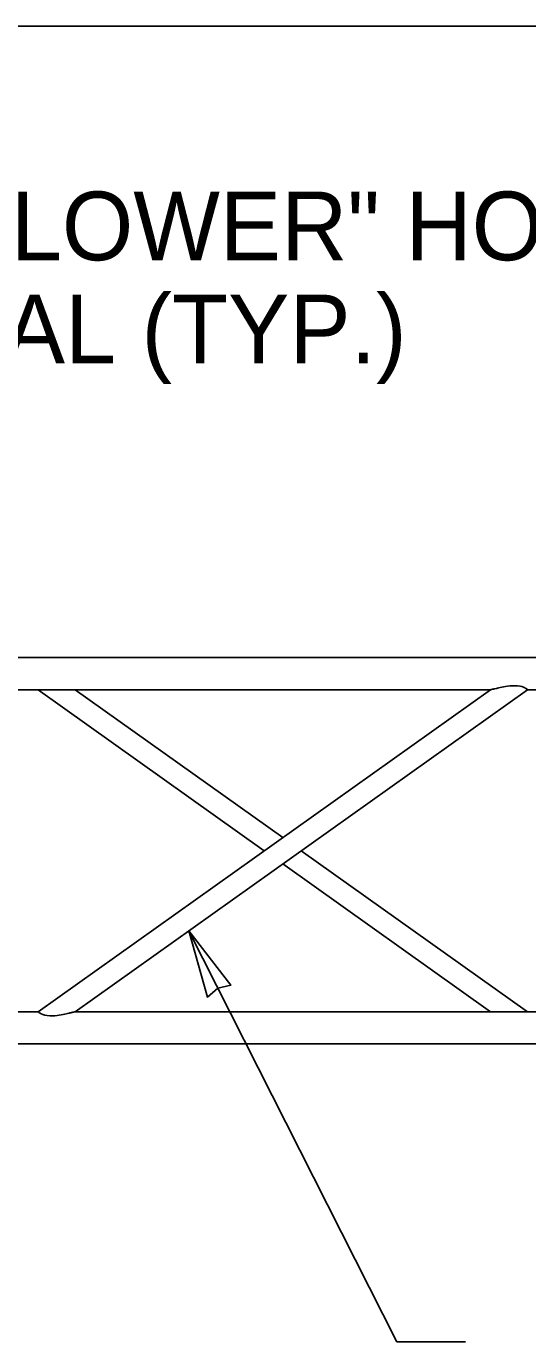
# Model space of a CAD drawing. Extents: x 99862 to 104211, y 98939 to 111076.
# Drawn here: x 101548.3 to 101665.2, y 101768.6 to 102075 of the extents above; entities that cross this region are included whole.
import ezdxf

# ---------------------------------------------------------------- set-up
doc = ezdxf.new("R2010")
doc.units = 0
for name, color, linetype in [('Level 15', 7, 'Continuous'), ('Level 20', 7, 'Continuous'), ('Level 6', 7, 'Continuous'), ('Level 60', 7, 'Continuous')]:
    doc.layers.add(name, color=color, linetype=linetype)

msp = doc.modelspace()

# ---------------------------------------------------------------- linework, layer by layer
at = {"layer": 'Level 15'}
for p in [(101586.13, 101864.31), (101650.65, 101768.61)]:
    msp.add_line(p, (101634.65, 101768.61), dxfattribs=at)
msp.add_lwpolyline([(101586.13, 101864.31), (101590.47, 101848.89), (101592.9, 101850.93), (101595.98, 101851.67)], close=True, dxfattribs=at)
at = {"layer": 'Level 6'}
for p, q in [((101808.38, 101927.97), (100925.37, 101927.97)), ((101656.49, 101920.47), (101440.59, 101920.47)), ((101551, 101920.47), (101603.75, 101882.97)), ((101551, 101845.47), (101656.49, 101920.47)), ((101559.63, 101920.47), (101608.06, 101886.04)), ((101559.63, 101845.47), (101665.12, 101920.47)), ((101673.92, 101920.47), (101665.12, 101920.47)), ((101612.38, 101882.97), (101665.12, 101845.47)), ((101608.06, 101879.9), (101656.49, 101845.47)), ((101551, 101845.47), (101546.08, 101845.47)), ((101779.42, 101845.47), (101559.63, 101845.47)), ((101808.38, 101837.97), (100925.37, 101837.97))]:
    msp.add_line(p, q, dxfattribs=at)
for points, degree in [([(101665.12, 101920.47), (101665.13, 101920.47), (101665.1, 101920.46), (101664.97, 101920.7), (101663.57, 101921.45), (101660.85, 101921.41), (101659.12, 101921.09), (101657.67, 101920.75), (101657.33, 101920.67), (101657.03, 101920.6), (101656.8, 101920.54), (101656.63, 101920.5), (101656.54, 101920.48), (101656.5, 101920.47), (101656.5, 101920.47), (101656.49, 101920.47)], 3), ([(101656.49, 101920.47), (101656.5, 101920.47), (101656.5, 101920.47), (101656.5, 101920.47)], 2), ([(101665.12, 101920.47), (101665.12, 101920.47), (101665.12, 101920.47), (101665.12, 101920.47)], 2), ([(101551, 101845.47), (101551, 101845.47), (101551, 101845.47), (101551.01, 101845.47)], 2), ([(101559.63, 101845.47), (101559.62, 101845.47), (101559.6, 101845.46), (101559.49, 101845.44), (101559.32, 101845.39), (101559.09, 101845.34), (101558.79, 101845.26), (101558.45, 101845.18), (101558.06, 101845.09), (101556.44, 101844.77), (101554.47, 101844.34), (101551.78, 101844.77), (101551.02, 101845.45), (101551, 101845.46), (101551, 101845.47), (101551, 101845.47)], 3), ([(101559.59, 101845.46), (101559.61, 101845.47), (101559.62, 101845.47), (101559.63, 101845.47)], 2)]:
    msp.add_open_spline(points, degree=degree, dxfattribs=at)
at = {"layer": 'Level 60'}
msp.add_line((103150, 102075), (100000, 102075), dxfattribs=at)

# ---------------------------------------------------------------- texts
at = {"layer": 'Level 20'}
for s, p in [('TRUSS "LOWER" HORIZONTAL', (101458.61, 102020.5)), ('DIAGONAL (TYP.)', (101458.61, 101996.5))]:
    msp.add_text(s, height=16, rotation=360, dxfattribs=at).set_placement(p)

doc.saveas('drawing.dxf')
